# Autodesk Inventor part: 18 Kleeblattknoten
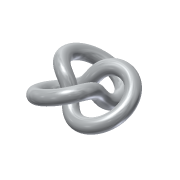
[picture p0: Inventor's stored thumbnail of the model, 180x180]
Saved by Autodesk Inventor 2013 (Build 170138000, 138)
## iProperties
Created: 2012-10
Part Number: 18 Kleeblattknoten
Material: Allgemein
Vendor: www.inventor-faq.de
Document SubType Name: Modeling
Designer: Administrator
Manufacturer: www.inventor-faq.de
Density: 1 g/cm^3
RuleStatus: InUse
AfterDocOpen0: inventorfaq
BeforeDocSave0: inventorfaq
Author: Administrator
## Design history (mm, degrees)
node "3D-Skizze1"
  node "3D-Gleichungskurve1" dims "d0" = 0, "d1" = 3600
workplane "Arbeitsebene1"
sketch "Skizze2"
  geometry: C1 r 0.5 at (0, 0); 2 further points
  constraints: 1 centre point, 1 coincident
  dimensions: "d2" = 1 diameter of C1
feature "Sweeping1" sketch "Skizze2" dims "d3" = 0
node "Volumenkörper1"
